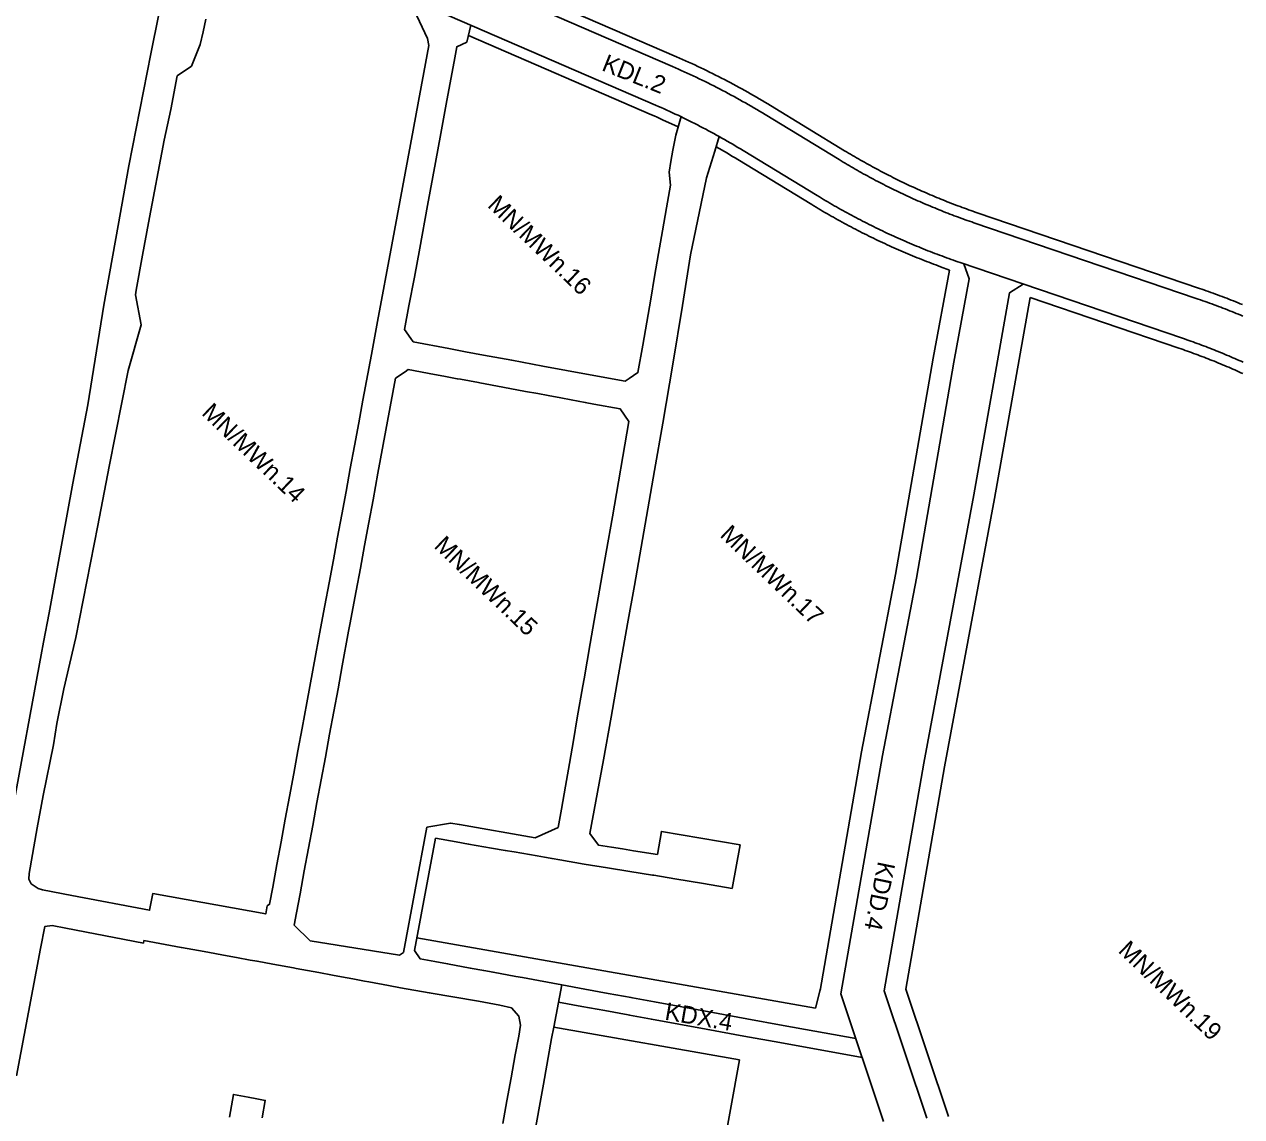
# Model space of a CAD drawing. Extents: x 7420063 to 7422255, y 5550978 to 5552824.
# Drawn here: x 7421663.8 to 7422010.7, y 5551292.7 to 5551603.9 of the extents above; entities that cross this region are included whole.
import ezdxf

# ---------------------------------------------------------------- set-up
doc = ezdxf.new("R2010")
doc.units = 0
for name, color, linetype in [('linie_rozgraniczajace', 7, 'Continuous'), ('linie_zabudowy_nieprzekraczalne', 7, 'Continuous'), ('oznaczenia_przeznaczen', 7, 'Continuous')]:
    doc.layers.add(name, color=color, linetype=linetype)

msp = doc.modelspace()

# ---------------------------------------------------------------- linework, layer by layer
at = {"layer": 'linie_rozgraniczajace'}
for p, q in [((7421789.84, 5551598.78), (7421791.03, 5551603.71)), ((7421849.49, 5551572.36), (7421850.93, 5551577.6)), ((7421860.55, 5551567.77), (7421861.84, 5551571.93)), ((7421908.66, 5551291.35), (7421896.5, 5551327.67)), ((7421921.01, 5551292.26), (7421908.84, 5551328.6))]:
    msp.add_line(p, q, dxfattribs=at)
for points in [[(7421660.29, 5551379.47), (7421668.57, 5551424.32), (7421669.22, 5551427.87), (7421670.86, 5551436.29), (7421673.08, 5551448.75), (7421677.58, 5551473.19), (7421681.83, 5551495.53), (7421686.41, 5551523.87), (7421690.51, 5551546.6), (7421693.51, 5551563.62), (7421699.84, 5551595.51), (7421704.25, 5551617.7), (7421707.49, 5551627.54), (7421708.84, 5551630.86), (7421709.06, 5551633.71)], [(7421757.27, 5551631.42), (7421848.47, 5551591.89), (7421849.31, 5551591.52), (7421850.16, 5551591.15), (7421851.01, 5551590.77), (7421851.86, 5551590.38), (7421852.71, 5551590), (7421853.56, 5551589.61), (7421854.4, 5551589.21), (7421855.24, 5551588.81), (7421856.08, 5551588.41), (7421856.92, 5551588.01), (7421857.76, 5551587.6), (7421858.6, 5551587.19), (7421859.43, 5551586.77), (7421860.26, 5551586.35), (7421861.09, 5551585.93), (7421861.92, 5551585.5), (7421862.75, 5551585.07), (7421863.57, 5551584.63), (7421864.39, 5551584.2), (7421865.22, 5551583.76), (7421866.03, 5551583.31), (7421866.85, 5551582.86), (7421867.67, 5551582.41), (7421868.48, 5551581.96), (7421869.29, 5551581.5), (7421870.1, 5551581.04), (7421870.91, 5551580.57), (7421871.71, 5551580.1), (7421872.51, 5551579.63), (7421873.31, 5551579.15), (7421874.11, 5551578.67), (7421874.9, 5551578.19), (7421895.99, 5551565.35), (7421896.56, 5551565), (7421897.13, 5551564.66), (7421897.7, 5551564.32), (7421898.27, 5551563.98), (7421898.84, 5551563.65), (7421899.41, 5551563.31), (7421899.99, 5551562.98), (7421900.56, 5551562.65), (7421901.14, 5551562.32), (7421901.72, 5551562), (7421902.3, 5551561.67), (7421902.88, 5551561.35), (7421903.46, 5551561.03), (7421904.04, 5551560.71), (7421904.62, 5551560.39), (7421905.21, 5551560.08), (7421905.79, 5551559.76), (7421906.38, 5551559.45), (7421906.97, 5551559.14), (7421907.56, 5551558.84), (7421908.15, 5551558.53), (7421908.74, 5551558.23), (7421909.33, 5551557.93), (7421909.92, 5551557.63), (7421910.52, 5551557.33), (7421911.11, 5551557.04), (7421911.71, 5551556.75), (7421912.31, 5551556.46), (7421912.9, 5551556.17), (7421913.5, 5551555.88), (7421914.1, 5551555.6), (7421914.71, 5551555.31), (7421915.31, 5551555.03), (7421915.91, 5551554.75), (7421916.51, 5551554.48), (7421917.12, 5551554.2), (7421917.73, 5551553.93), (7421918.33, 5551553.66), (7421918.94, 5551553.39), (7421919.55, 5551553.13), (7421920.16, 5551552.86), (7421920.77, 5551552.6), (7421921.38, 5551552.34), (7421921.99, 5551552.08), (7421922.61, 5551551.83), (7421923.22, 5551551.58), (7421923.83, 5551551.32), (7421924.45, 5551551.08), (7421925.07, 5551550.83), (7421925.68, 5551550.58), (7421926.3, 5551550.34), (7421926.92, 5551550.1), (7421927.54, 5551549.86), (7421928.16, 5551549.63), (7421928.78, 5551549.39), (7421929.4, 5551549.16), (7421930.02, 5551548.93), (7421930.65, 5551548.7), (7421931.27, 5551548.48), (7421931.89, 5551548.25), (7421932.52, 5551548.03), (7421933.14, 5551547.81), (7421933.77, 5551547.6), (7421934.4, 5551547.38), (7421997.69, 5551525.84), (7421998.33, 5551525.62), (7421998.97, 5551525.4), (7421999.62, 5551525.17), (7422000.26, 5551524.95), (7422000.9, 5551524.72), (7422001.54, 5551524.49), (7422002.18, 5551524.25), (7422002.82, 5551524.02), (7422003.46, 5551523.78), (7422004.1, 5551523.54), (7422004.73, 5551523.3), (7422005.37, 5551523.05), (7422006, 5551522.81), (7422006.64, 5551522.56), (7422007.27, 5551522.31), (7422007.91, 5551522.06), (7422008.54, 5551521.8), (7422009.17, 5551521.55), (7422009.8, 5551521.29), (7422010.43, 5551521.03), (7422011.06, 5551520.76)], [(7421752.51, 5551620.41), (7421843.68, 5551580.89), (7421844.49, 5551580.53), (7421845.3, 5551580.18), (7421846.1, 5551579.82), (7421846.9, 5551579.46), (7421847.7, 5551579.09), (7421848.5, 5551578.72), (7421849.3, 5551578.35), (7421850.09, 5551577.98), (7421850.89, 5551577.6), (7421851.68, 5551577.21), (7421852.47, 5551576.83), (7421853.26, 5551576.44), (7421854.05, 5551576.04), (7421854.83, 5551575.65), (7421855.62, 5551575.25), (7421856.4, 5551574.84), (7421857.18, 5551574.44), (7421857.96, 5551574.03), (7421858.74, 5551573.61), (7421859.51, 5551573.2), (7421860.29, 5551572.78), (7421861.06, 5551572.35), (7421861.83, 5551571.93), (7421862.59, 5551571.5), (7421863.36, 5551571.07), (7421864.12, 5551570.63), (7421864.89, 5551570.19), (7421865.65, 5551569.75), (7421866.4, 5551569.3), (7421867.16, 5551568.85), (7421867.91, 5551568.4), (7421868.67, 5551567.94), (7421889.76, 5551555.1), (7421890.36, 5551554.73), (7421890.96, 5551554.37), (7421891.56, 5551554.01), (7421892.17, 5551553.65), (7421892.78, 5551553.29), (7421893.38, 5551552.94), (7421893.99, 5551552.59), (7421894.6, 5551552.23), (7421895.22, 5551551.89), (7421895.83, 5551551.54), (7421896.44, 5551551.19), (7421897.06, 5551550.85), (7421897.68, 5551550.51), (7421898.29, 5551550.17), (7421898.91, 5551549.84), (7421899.53, 5551549.5), (7421900.16, 5551549.17), (7421900.78, 5551548.84), (7421901.4, 5551548.51), (7421902.03, 5551548.19), (7421902.66, 5551547.86), (7421903.28, 5551547.54), (7421903.91, 5551547.22), (7421904.54, 5551546.9), (7421905.17, 5551546.59), (7421905.8, 5551546.28), (7421906.44, 5551545.97), (7421907.07, 5551545.66), (7421907.71, 5551545.35), (7421908.34, 5551545.05), (7421908.98, 5551544.74), (7421909.62, 5551544.44), (7421910.26, 5551544.15), (7421910.9, 5551543.85), (7421911.54, 5551543.56), (7421912.18, 5551543.27), (7421912.83, 5551542.98), (7421913.47, 5551542.69), (7421914.12, 5551542.4), (7421914.76, 5551542.12), (7421915.41, 5551541.84), (7421916.06, 5551541.56), (7421916.71, 5551541.29), (7421917.36, 5551541.02), (7421918.01, 5551540.74), (7421918.66, 5551540.48), (7421919.31, 5551540.21), (7421919.97, 5551539.94), (7421920.62, 5551539.68), (7421921.28, 5551539.42), (7421921.93, 5551539.16), (7421922.59, 5551538.91), (7421923.25, 5551538.66), (7421923.91, 5551538.41), (7421924.56, 5551538.16), (7421925.22, 5551537.91), (7421925.89, 5551537.67), (7421926.55, 5551537.42), (7421927.21, 5551537.19), (7421927.87, 5551536.95), (7421928.54, 5551536.71), (7421929.2, 5551536.48), (7421929.86, 5551536.25), (7421930.52, 5551536.02), (7421993.81, 5551514.48), (7421994.43, 5551514.27), (7421995.03, 5551514.06), (7421995.64, 5551513.85), (7421996.24, 5551513.64), (7421996.84, 5551513.42), (7421997.45, 5551513.2), (7421998.05, 5551512.98), (7421998.65, 5551512.76), (7421999.25, 5551512.54), (7421999.85, 5551512.31), (7422000.45, 5551512.09), (7422001.05, 5551511.86), (7422001.65, 5551511.62), (7422002.25, 5551511.39), (7422002.85, 5551511.15), (7422003.44, 5551510.92), (7422004.04, 5551510.68), (7422004.64, 5551510.44), (7422005.23, 5551510.19), (7422005.82, 5551509.95), (7422006.42, 5551509.7), (7422007.01, 5551509.45), (7422007.6, 5551509.2), (7422008.19, 5551508.94), (7422008.78, 5551508.69), (7422009.37, 5551508.43), (7422009.96, 5551508.17), (7422010.54, 5551507.91), (7422011.13, 5551507.65)], [(7421715.46, 5551605.42), (7421714.69, 5551601.79), (7421713.91, 5551598.17), (7421711.38, 5551592.03), (7421707.28, 5551589.21), (7421705.52, 5551579.68), (7421703.63, 5551570.87), (7421699.18, 5551547.4), (7421697.46, 5551538.15), (7421695.61, 5551528.15), (7421695.49, 5551526.85), (7421697.03, 5551518.33), (7421693.4, 5551505.32), (7421687.94, 5551477.92), (7421684.73, 5551461.12), (7421678.45, 5551429.19), (7421675.02, 5551414.57), (7421673.07, 5551404.7), (7421672.06, 5551398.69), (7421669.14, 5551384.24), (7421667.39, 5551375), (7421665.17, 5551361.95), (7421665.06, 5551360.38), (7421665.69, 5551359.09), (7421667.74, 5551357.72), (7421668.92, 5551357.32), (7421677.26, 5551355.74), (7421699.47, 5551351.52), (7421700.39, 5551356.28), (7421732.55, 5551350.47), (7421732.96, 5551352.75), (7421733.65, 5551353.21), (7421734.55, 5551358.09), (7421735.74, 5551364.53), (7421736.95, 5551371.01), (7421738.15, 5551377.47), (7421739.35, 5551383.96), (7421740.55, 5551390.43), (7421741.75, 5551396.92), (7421742.95, 5551403.38), (7421744.29, 5551410.63), (7421746.88, 5551424.56), (7421748.22, 5551431.79), (7421749.43, 5551438.34), (7421750.63, 5551444.82), (7421751.84, 5551451.32), (7421753.04, 5551457.8), (7421754.24, 5551464.3), (7421755.45, 5551470.83), (7421756.66, 5551477.36), (7421757.85, 5551483.81), (7421759.07, 5551490.35), (7421760.27, 5551496.83), (7421762.67, 5551509.81), (7421764.43, 5551519.26), (7421768.48, 5551541.1), (7421774.54, 5551573.77), (7421776.06, 5551581.99), (7421777.58, 5551590.18), (7421779.01, 5551597.86), (7421778.71, 5551599.88), (7421773.26, 5551611.41)], [(7421849.49, 5551572.36), (7421849.21, 5551571.4), (7421848.63, 5551568.09), (7421848.06, 5551564.79), (7421847.55, 5551561.83), (7421847.92, 5551558.12), (7421846.79, 5551551.61), (7421845.67, 5551545.1), (7421844.54, 5551538.59), (7421843.4, 5551532.07), (7421842.28, 5551525.56), (7421841.15, 5551519.04), (7421840.02, 5551512.53), (7421838.66, 5551504.69), (7421836.17, 5551502.97), (7421835.05, 5551502.2), (7421825.06, 5551504.05), (7421811.58, 5551506.54), (7421802.7, 5551508.19), (7421794.6, 5551509.7), (7421789.49, 5551510.65), (7421784.77, 5551511.52), (7421774.62, 5551513.41), (7421773.96, 5551514.36), (7421772.15, 5551517), (7421773.39, 5551523.67), (7421774.92, 5551531.9), (7421776.44, 5551540.16), (7421778.7, 5551552.33), (7421780.97, 5551564.57), (7421782.49, 5551572.82), (7421784.03, 5551581.12), (7421786.48, 5551594.33), (7421787, 5551597.54), (7421789.84, 5551598.78)], [(7421865.47, 5551357.72), (7421867.75, 5551370.11), (7421845.35, 5551374), (7421844.21, 5551367.41), (7421837.4, 5551368.49), (7421834.25, 5551368.99), (7421831.11, 5551369.48), (7421827.38, 5551370.07), (7421824.96, 5551373.43), (7421828.84, 5551394.36), (7421830.99, 5551406.49), (7421833.13, 5551418.62), (7421835.68, 5551433.11), (7421837.62, 5551444.04), (7421839.55, 5551454.97), (7421841.47, 5551465.9), (7421843.4, 5551476.83), (7421845.78, 5551490.3), (7421848.57, 5551507.05), (7421851.36, 5551523.8), (7421853.58, 5551538.21), (7421858.19, 5551560.2), (7421860.55, 5551567.77)], [(7421931.49, 5551535.7), (7421933.06, 5551531.36), (7421928.64, 5551507.65), (7421918, 5551446.12), (7421908.3, 5551395.59), (7421896.5, 5551327.67)], [(7421908.84, 5551328.6), (7421920.1, 5551393.43), (7421934.4, 5551469.87), (7421944.54, 5551527.43), (7421948.47, 5551529.92)], [(7421815.94, 5551375.12), (7421816.84, 5551380.34), (7421817.98, 5551386.84), (7421819.11, 5551393.34), (7421820.25, 5551399.84), (7421821.37, 5551406.34), (7421822.96, 5551415.46), (7421823.31, 5551417.43), (7421825.07, 5551427.54), (7421826.19, 5551434.05), (7421827.32, 5551440.54), (7421828.46, 5551447.04), (7421829.59, 5551453.54), (7421831.35, 5551463.62), (7421836.06, 5551490.75), (7421833.59, 5551494.33), (7421826.08, 5551495.73), (7421823.62, 5551496.19), (7421819.58, 5551496.94), (7421816.63, 5551497.49), (7421813.1, 5551498.14), (7421810.15, 5551498.69), (7421806.6, 5551499.34), (7421800.12, 5551500.54), (7421793.62, 5551501.75), (7421793.24, 5551501.82), (7421788.1, 5551502.77), (7421787.14, 5551502.95), (7421783.34, 5551503.65), (7421780.65, 5551504.16), (7421773.15, 5551505.54), (7421772.29, 5551504.95), (7421769.56, 5551503.08), (7421764.55, 5551476.02), (7421763.14, 5551468.43), (7421761.94, 5551461.95), (7421760.74, 5551455.45), (7421759.54, 5551448.97), (7421758.33, 5551442.47), (7421756.57, 5551432.95), (7421756.2, 5551430.99), (7421754.37, 5551421.13), (7421753.17, 5551414.64), (7421751.97, 5551408.15), (7421750.77, 5551401.65), (7421749.56, 5551395.16), (7421748.36, 5551388.68), (7421747.16, 5551382.18), (7421745.96, 5551375.7), (7421744.75, 5551369.21), (7421743.54, 5551362.72), (7421742.34, 5551356.23), (7421741.34, 5551350.83), (7421740.68, 5551347.24), (7421745.24, 5551342.78), (7421770.68, 5551338.77), (7421771.81, 5551339.52), (7421778.51, 5551375.16), (7421785.23, 5551376.36), (7421787.75, 5551375.92), (7421809.33, 5551372.16), (7421815.94, 5551375.12)], [(7421776.58, 5551337.69), (7421774.97, 5551340.02), (7421780.96, 5551372.04)], [(7421808.75, 5551285.76), (7421811.7, 5551302.02), (7421814.04, 5551315), (7421814.67, 5551318.23), (7421816.91, 5551330.27), (7421810.34, 5551331.48), (7421805.77, 5551332.32), (7421803.85, 5551332.67), (7421797.36, 5551333.86), (7421794.69, 5551334.35), (7421790.87, 5551335.06), (7421784.38, 5551336.26), (7421780.72, 5551336.93), (7421776.58, 5551337.69), (7421774.97, 5551340.02), (7421780.96, 5551372.04), (7421786.85, 5551371), (7421790.4, 5551370.39), (7421796.9, 5551369.25), (7421800.82, 5551368.57), (7421803.4, 5551368.12), (7421809.9, 5551366.99), (7421812.06, 5551366.61), (7421816.4, 5551365.85), (7421823.33, 5551364.64), (7421830, 5551363.58), (7421836.36, 5551362.57), (7421842.76, 5551361.56), (7421843.18, 5551361.5), (7421849.17, 5551360.48), (7421857.32, 5551359.1), (7421865.47, 5551357.72)], [(7421814.06, 5551366.26), (7421812.06, 5551366.61), (7421809.9, 5551366.99), (7421803.4, 5551368.12), (7421800.82, 5551368.57), (7421796.9, 5551369.25), (7421790.4, 5551370.39), (7421786.85, 5551371), (7421780.96, 5551372.04)], [(7421661.52, 5551304.37), (7421664.97, 5551322.5), (7421668.42, 5551340.63), (7421669.63, 5551346.92), (7421671.7, 5551347.13), (7421675.62, 5551346.38), (7421697.69, 5551342.18), (7421697.83, 5551342.89), (7421708.43, 5551340.95), (7421708.56, 5551340.93), (7421715.05, 5551339.74), (7421721.55, 5551338.54), (7421724.24, 5551338.05), (7421728.13, 5551337.34), (7421730.12, 5551336.97), (7421734.62, 5551336.14), (7421740.51, 5551335.07), (7421741.22, 5551334.94), (7421747.71, 5551333.74), (7421751.58, 5551333.03), (7421754.19, 5551332.55), (7421757.36, 5551331.97), (7421760.69, 5551331.35), (7421761.96, 5551331.12), (7421767.54, 5551330.1), (7421771.02, 5551329.46), (7421779.17, 5551328.04), (7421793.16, 5551325.59), (7421799.27, 5551324.46), (7421802.63, 5551323.68), (7421804.69, 5551321.32), (7421805.18, 5551318.81), (7421804.66, 5551315.67), (7421803.69, 5551310.33), (7421802.5, 5551303.76), (7421801.32, 5551297.27), (7421800.14, 5551290.78)], [(7421761.56, 5551027.07), (7421762.48, 5551032.01), (7421764.74, 5551044.23), (7421775.26, 5551100.59), (7421785.78, 5551156.95), (7421791.84, 5551191.39), (7421797.91, 5551225.83), (7421803.33, 5551255.79), (7421808.75, 5551285.76), (7421811.7, 5551302.02), (7421814.04, 5551315), (7421814.67, 5551318.23), (7421816.91, 5551330.27), (7421810.34, 5551331.48), (7421805.77, 5551332.32), (7421803.85, 5551332.67), (7421797.36, 5551333.86), (7421794.69, 5551334.35), (7421790.87, 5551335.06), (7421784.38, 5551336.26), (7421780.72, 5551336.93), (7421776.58, 5551337.69)], [(7421816.91, 5551330.27), (7421823.54, 5551329.05), (7421830.13, 5551327.84), (7421836.69, 5551326.63), (7421837.08, 5551326.57), (7421843.38, 5551325.41), (7421858.98, 5551322.56), (7421869.69, 5551320.6), (7421880, 5551318.72), (7421900.75, 5551314.96)], [(7421816, 5551325.35), (7421822.64, 5551324.13), (7421829.23, 5551322.92), (7421835.86, 5551321.7), (7421836.25, 5551321.64), (7421842.48, 5551320.49), (7421858.08, 5551317.64), (7421868.79, 5551315.68), (7421879.11, 5551313.8), (7421902.56, 5551309.56)], [(7421814.67, 5551318.23), (7421867.63, 5551308.95)], [(7421867.63, 5551308.95), (7421857.71, 5551254.35), (7421873.22, 5551251.63), (7421900.89, 5551246.97)], [(7421731.52, 5551292.36), (7421732.44, 5551297.34), (7421729.99, 5551297.82), (7421727.53, 5551298.29), (7421723.34, 5551299.03), (7421722.23, 5551292.58)]]:
    msp.add_lwpolyline(points, dxfattribs=at)
at = {"layer": 'linie_zabudowy_nieprzekraczalne'}
for p, q in [((7421775.65, 5551343.63), (7421889.22, 5551323.63)), ((7421915.01, 5551329.07), (7421927.19, 5551292.72))]:
    msp.add_line(p, q, dxfattribs=at)
for points in [[(7421758.46, 5551634.18), (7421849.66, 5551594.64), (7421850.52, 5551594.27), (7421851.38, 5551593.89), (7421852.24, 5551593.5), (7421853.1, 5551593.12), (7421853.96, 5551592.72), (7421854.82, 5551592.33), (7421855.68, 5551591.93), (7421856.53, 5551591.52), (7421857.38, 5551591.12), (7421858.23, 5551590.71), (7421859.08, 5551590.29), (7421859.93, 5551589.87), (7421860.77, 5551589.45), (7421861.62, 5551589.03), (7421862.46, 5551588.6), (7421863.3, 5551588.16), (7421864.14, 5551587.73), (7421864.97, 5551587.29), (7421865.81, 5551586.84), (7421866.64, 5551586.4), (7421867.47, 5551585.94), (7421868.3, 5551585.49), (7421869.13, 5551585.03), (7421869.95, 5551584.57), (7421870.77, 5551584.11), (7421871.59, 5551583.64), (7421872.41, 5551583.17), (7421873.23, 5551582.69), (7421874.04, 5551582.21), (7421874.85, 5551581.73), (7421875.66, 5551581.24), (7421876.46, 5551580.76), (7421897.55, 5551567.91), (7421898.12, 5551567.57), (7421898.67, 5551567.23), (7421899.23, 5551566.9), (7421899.8, 5551566.57), (7421900.36, 5551566.24), (7421900.92, 5551565.91), (7421901.49, 5551565.58), (7421902.05, 5551565.25), (7421902.62, 5551564.93), (7421903.19, 5551564.61), (7421903.76, 5551564.29), (7421904.33, 5551563.97), (7421904.9, 5551563.66), (7421905.48, 5551563.34), (7421906.05, 5551563.03), (7421906.63, 5551562.72), (7421907.2, 5551562.41), (7421907.78, 5551562.11), (7421908.36, 5551561.8), (7421908.94, 5551561.5), (7421909.52, 5551561.2), (7421910.1, 5551560.9), (7421910.68, 5551560.61), (7421911.27, 5551560.31), (7421911.85, 5551560.02), (7421912.44, 5551559.73), (7421913.03, 5551559.44), (7421913.61, 5551559.16), (7421914.2, 5551558.87), (7421914.79, 5551558.59), (7421915.38, 5551558.31), (7421915.98, 5551558.03), (7421916.57, 5551557.75), (7421917.16, 5551557.48), (7421917.76, 5551557.21), (7421918.35, 5551556.94), (7421918.95, 5551556.67), (7421919.55, 5551556.4), (7421920.15, 5551556.14), (7421920.75, 5551555.88), (7421921.35, 5551555.62), (7421921.95, 5551555.36), (7421922.55, 5551555.11), (7421923.15, 5551554.85), (7421923.75, 5551554.6), (7421924.36, 5551554.35), (7421924.96, 5551554.1), (7421925.57, 5551553.86), (7421926.18, 5551553.62), (7421926.78, 5551553.37), (7421927.39, 5551553.14), (7421928, 5551552.9), (7421928.61, 5551552.66), (7421929.22, 5551552.43), (7421929.83, 5551552.2), (7421930.44, 5551551.97), (7421931.06, 5551551.75), (7421931.67, 5551551.52), (7421932.28, 5551551.3), (7421932.9, 5551551.08), (7421933.51, 5551550.86), (7421934.13, 5551550.65), (7421934.75, 5551550.43), (7421935.37, 5551550.22), (7421998.66, 5551528.68), (7421999.31, 5551528.46), (7421999.96, 5551528.23), (7422000.61, 5551528), (7422001.26, 5551527.77), (7422001.91, 5551527.54), (7422002.56, 5551527.31), (7422003.21, 5551527.07), (7422003.86, 5551526.83), (7422004.51, 5551526.59), (7422005.16, 5551526.35), (7422005.8, 5551526.1), (7422006.45, 5551525.85), (7422007.09, 5551525.6), (7422007.74, 5551525.35), (7422008.38, 5551525.1), (7422009.02, 5551524.84), (7422009.66, 5551524.58), (7422010.31, 5551524.32), (7422010.95, 5551524.06)], [(7421850.13, 5551574.69), (7421845.66, 5551576.73), (7421844.87, 5551577.08), (7421844.08, 5551577.44), (7421843.29, 5551577.79), (7421842.48, 5551578.14), (7421790.32, 5551600.75)], [(7421927.43, 5551533.91), (7421924.85, 5551534.85), (7421924.18, 5551535.1), (7421923.51, 5551535.35), (7421922.84, 5551535.6), (7421922.17, 5551535.85), (7421921.51, 5551536.11), (7421920.84, 5551536.37), (7421920.18, 5551536.63), (7421919.51, 5551536.9), (7421918.85, 5551537.16), (7421918.18, 5551537.43), (7421917.52, 5551537.7), (7421916.86, 5551537.97), (7421916.2, 5551538.25), (7421915.54, 5551538.53), (7421914.88, 5551538.81), (7421914.22, 5551539.09), (7421913.57, 5551539.37), (7421912.91, 5551539.66), (7421912.26, 5551539.95), (7421911.6, 5551540.24), (7421910.95, 5551540.53), (7421910.3, 5551540.83), (7421909.65, 5551541.12), (7421909, 5551541.42), (7421908.35, 5551541.73), (7421907.7, 5551542.03), (7421907.05, 5551542.34), (7421906.41, 5551542.65), (7421905.76, 5551542.96), (7421905.12, 5551543.27), (7421904.48, 5551543.59), (7421903.84, 5551543.9), (7421903.2, 5551544.22), (7421902.56, 5551544.54), (7421901.92, 5551544.87), (7421901.28, 5551545.2), (7421900.65, 5551545.52), (7421900.01, 5551545.85), (7421899.38, 5551546.19), (7421898.75, 5551546.52), (7421898.12, 5551546.86), (7421897.49, 5551547.2), (7421896.86, 5551547.54), (7421896.23, 5551547.88), (7421895.61, 5551548.23), (7421894.98, 5551548.58), (7421894.36, 5551548.93), (7421893.74, 5551549.28), (7421893.11, 5551549.63), (7421892.49, 5551549.99), (7421891.88, 5551550.34), (7421891.26, 5551550.7), (7421890.64, 5551551.07), (7421890.03, 5551551.43), (7421889.42, 5551551.8), (7421888.81, 5551552.17), (7421888.2, 5551552.53), (7421867.11, 5551565.38), (7421866.36, 5551565.83), (7421865.62, 5551566.28), (7421864.88, 5551566.72), (7421864.13, 5551567.16), (7421860.94, 5551569.02)], [(7421890.59, 5551328.69), (7421902.4, 5551396.67), (7421912.09, 5551447.19), (7421922.75, 5551508.79), (7421927.43, 5551533.91)], [(7421950.46, 5551526.07), (7421940.31, 5551468.8), (7421926.01, 5551392.37), (7421915.01, 5551329.07)], [(7422011.05, 5551504.39), (7422010.47, 5551504.65), (7422009.89, 5551504.91), (7422009.32, 5551505.17), (7422008.74, 5551505.43), (7422008.16, 5551505.68), (7422007.58, 5551505.94), (7422007, 5551506.19), (7422006.42, 5551506.44), (7422005.84, 5551506.69), (7422005.25, 5551506.93), (7422004.67, 5551507.18), (7422004.09, 5551507.42), (7422003.5, 5551507.66), (7422002.92, 5551507.9), (7422002.33, 5551508.13), (7422001.74, 5551508.37), (7422001.15, 5551508.6), (7422000.57, 5551508.83), (7421999.98, 5551509.06), (7421999.39, 5551509.28), (7421998.79, 5551509.51), (7421998.2, 5551509.73), (7421997.61, 5551509.95), (7421997.02, 5551510.17), (7421996.43, 5551510.38), (7421995.83, 5551510.6), (7421995.24, 5551510.81), (7421994.64, 5551511.02), (7421994.05, 5551511.23), (7421993.45, 5551511.44), (7421992.84, 5551511.64), (7421950.46, 5551526.07)], [(7421890.7, 5551329.2), (7421889.22, 5551323.63)]]:
    msp.add_lwpolyline(points, dxfattribs=at)

# ---------------------------------------------------------------- texts
at = {"layer": 'oznaczenia_przeznaczen'}
for s, rotation, p in [('KDL.2', 338.1773, (7421828.04, 5551590.89)), ('MN/MWn.16', 316.2133, (7421795.54, 5551552.09)), ('MN/MWn.14', 316.2133, (7421714.03, 5551492.87)), ('MN/MWn.17', 316.2133, (7421861.74, 5551458.13)), ('MN/MWn.15', 316.2133, (7421780.28, 5551455.01)), ('KDD.4', 258.3631, (7421907.11, 5551365.66)), ('MN/MWn.19', 316.2133, (7421975.26, 5551339.74)), ('KDX.4', 350.2478, (7421846.09, 5551320.39))]:
    msp.add_text(s, height=5, rotation=rotation, dxfattribs=at).set_placement(p)

doc.saveas('drawing.dxf')
